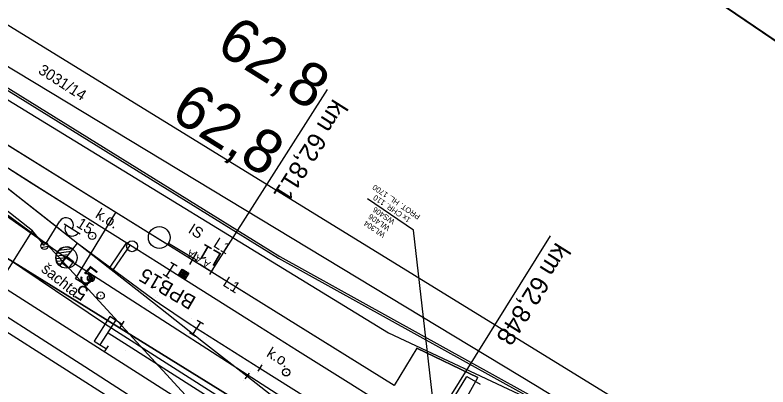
# Model space of a CAD drawing. Extents: x -621145 to -620110, y -1122807 to -1121971.
# Drawn here: x -620819.9 to -620716.5, y -1122376.5 to -1122325.4 of the extents above; entities that cross this region are included whole.
import ezdxf

# ---------------------------------------------------------------- set-up
doc = ezdxf.new("R2010")
doc.units = 0
for name, color, linetype in [('060601_EOV', 7, 'Continuous'), ('060604_ROZVODY_SEE', 7, 'Continuous'), ('CETIN', 7, 'Continuous'), ('POPIS KABELOVÉ TRASY', 7, 'Continuous'), ('PS 06-14-01_trasa_sdělovací_nové', 7, 'Continuous'), ('RÁMY', 7, 'Continuous'), ('SEE', 7, 'Continuous'), ('SSZT', 7, 'Continuous'), ('SSZT-DK', 7, 'Continuous'), ('UZEMNĚNÍ', 7, 'Continuous'), ('Vrstva 1', 7, 'Continuous'), ('Vrstva 15', 7, 'Continuous'), ('Vrstva 2', 7, 'Continuous'), ('Vrstva 25', 7, 'Continuous'), ('Vrstva 27', 7, 'Continuous'), ('Vrstva 3', 7, 'Continuous'), ('Vrstva 47', 7, 'Continuous'), ('Vrstva 53', 7, 'Continuous'), ('Vrstva 55', 7, 'Continuous'), ('Vrstva 56', 7, 'Continuous'), ('Vrstva 57', 7, 'Continuous'), ('Vrstva 6', 7, 'Continuous'), ('Vrstva 62', 7, 'Continuous'), ('Vrstva 7', 7, 'Continuous'), ('ČD-T', 7, 'Continuous')]:
    doc.layers.add(name, color=color, linetype=linetype)

msp = doc.modelspace()

# ---------------------------------------------------------------- linework, layer by layer
at = {"layer": '060601_EOV'}
msp.add_lwpolyline([(-620599.21, -1122483.22), (-620683.52, -1122429.44), (-620756.33, -1122383.52), (-620765.8, -1122398.39), (-620784.65, -1122386.39), (-620822.22, -1122362.42), (-620817.53, -1122355.08), (-620826.41, -1122348.08), (-620839.92, -1122337.94), (-620848.84, -1122332), (-620848.83, -1122331.99)], dxfattribs=at)
at = {"layer": '060604_ROZVODY_SEE'}
msp.add_line((-620815.89, -1122357.08), (-620817.53, -1122355.08), dxfattribs=at)
msp.add_lwpolyline([(-620742.35, -1122414.85), (-620741.73, -1122413.88), (-620750.53, -1122408.25), (-620763.56, -1122399.82), (-620784.65, -1122386.39), (-620822.22, -1122362.42), (-620817.53, -1122355.08), (-620826.41, -1122348.08), (-620839.92, -1122337.94), (-620854.57, -1122328.18), (-620868.06, -1122319.69), (-620885.37, -1122308.82), (-620912.87, -1122291.53), (-620913.33, -1122292.25)], dxfattribs=at)
at = {"layer": 'CETIN'}
msp.add_lwpolyline([(-620926.41, -1122268.7), (-620748.44, -1122376.27), (-620484.52, -1122538.15)], dxfattribs=at)
at = {"layer": 'POPIS KABELOVÉ TRASY'}
for points in [[(-620761.06, -1122390.96), (-620765.21, -1122354.95), (-620771.53, -1122350.65)], [(-620771.53, -1122350.65), (-620771.53, -1122350.65)]]:
    msp.add_lwpolyline(points, dxfattribs=at)
at = {"layer": 'PS 06-14-01_trasa_sdělovací_nové'}
msp.add_lwpolyline([(-620756.33, -1122383.52), (-620759.75, -1122381.36), (-620756.35, -1122375.21), (-620764.72, -1122371.2), (-620767.85, -1122376.3), (-620853.07, -1122323.34), (-620895.69, -1122296.63), (-620912.11, -1122286.23), (-620914.88, -1122290.62), (-620933.41, -1122279.02)], dxfattribs=at)
at = {"layer": 'RÁMY'}
for points in [[(-621061.56, -1122093.92), (-620192.94, -1122683.83), (-620276.37, -1122806.68), (-621144.99, -1122216.77)], [(-620717.54, -1122148.04), (-620630.68, -1122207.04), (-620714.11, -1122329.88), (-620800.97, -1122270.89)], [(-620887.83, -1122211.9), (-620192.94, -1122683.83), (-620276.37, -1122806.68), (-620971.26, -1122334.75)]]:
    msp.add_lwpolyline(points, close=True, dxfattribs=at)
at = {"layer": 'SEE'}
msp.add_lwpolyline([(-620611.37, -1122497.7), (-620665.57, -1122462.75), (-620686.03, -1122449.83), (-620727.54, -1122423.18), (-620794.51, -1122379.86), (-620815.52, -1122356.95), (-620832.17, -1122344.66), (-620847.81, -1122332.59), (-620908.26, -1122294.69)], dxfattribs=at)
at = {"layer": 'SSZT'}
for points in [[(-620879.24, -1122313.32), (-620842.99, -1122336.61), (-620835.05, -1122343.25), (-620812.66, -1122358.95), (-620764.9, -1122389.75), (-620688.59, -1122438.97), (-620596.98, -1122496.73), (-620576.74, -1122509.48), (-620506.75, -1122556.12), (-620447.29, -1122593.62), (-620363.27, -1122647.56), (-620313.97, -1122679.22), (-620306.51, -1122669.29), (-620273.14, -1122696.27), (-620258.42, -1122709.14), (-620248.07, -1122696.09)], [(-620763.25, -1122378.91), (-620761.03, -1122380.27), (-620757.87, -1122375.08), (-620756.04, -1122376.12)], [(-620763.25, -1122378.91), (-620761.03, -1122380.27), (-620757.87, -1122375.08), (-620756.04, -1122376.12)]]:
    msp.add_lwpolyline(points, dxfattribs=at)
at = {"layer": 'SSZT-DK'}
msp.add_lwpolyline([(-620927.29, -1122269.99), (-620900.27, -1122286.47), (-620889.15, -1122293.45), (-620783.74, -1122358.82), (-620712.75, -1122398.18), (-620653.12, -1122435.23), (-620617.36, -1122456.74), (-620574.42, -1122482.6), (-620528.16, -1122511.11), (-620496.31, -1122530.83), (-620515.02, -1122558.81), (-620500.38, -1122568.61), (-620465.39, -1122591.45), (-620452.16, -1122605.02), (-620438.23, -1122615.5), (-620392.31, -1122655.21), (-620359.04, -1122685.8), (-620308.77, -1122717.8), (-620291.41, -1122732.21), (-620277.2, -1122744.11), (-620257.61, -1122720.05), (-620250.25, -1122710.72), (-620233.29, -1122724.26), (-620225.35, -1122731.56)], dxfattribs=at)
at = {"layer": 'UZEMNĚNÍ'}
msp.add_line((-620815.89, -1122357.08), (-620817.53, -1122355.08), dxfattribs=at)
msp.add_lwpolyline([(-620742.35, -1122414.85), (-620741.73, -1122413.88), (-620750.53, -1122408.25), (-620763.56, -1122399.82), (-620784.65, -1122386.39), (-620822.22, -1122362.42), (-620817.53, -1122355.08), (-620826.41, -1122348.08), (-620838.67, -1122338.88), (-620840.23, -1122340.95)], dxfattribs=at)
at = {"layer": 'Vrstva 1'}
for p, q in [((-620806.11, -1122352.53), (-620848.09, -1122326.43)), ((-620811.62, -1122361.66), (-620806.11, -1122352.53)), ((-620764.72, -1122371.2), (-620756.35, -1122375.21))]:
    msp.add_line(p, q, dxfattribs=at)
for points in [[(-620931.81, -1122276.66), (-620929.02, -1122278.42), (-620921.28, -1122283.3), (-620914.45, -1122287.58), (-620907.38, -1122292.04), (-620900.38, -1122296.43), (-620893.37, -1122300.83), (-620887.01, -1122304.84), (-620881.07, -1122308.56), (-620874.8, -1122312.5), (-620868.33, -1122316.57), (-620865.13, -1122318.58), (-620858.38, -1122322.84), (-620854.48, -1122325.28), (-620853.21, -1122326.08), (-620851.73, -1122327.01), (-620850.55, -1122327.76), (-620840.58, -1122334.05), (-620833.63, -1122338.43), (-620832.14, -1122339.37), (-620823.78, -1122344.63), (-620817.74, -1122348.46), (-620811.37, -1122352.45)], [(-620851.64, -1122327.08), (-620840.38, -1122334.59), (-620831.19, -1122341.26), (-620824.9, -1122346.12), (-620811.35, -1122356.78), (-620800.85, -1122364.55), (-620800.09, -1122365.07), (-620796.17, -1122367.69), (-620795.02, -1122368.44), (-620786.31, -1122373.93), (-620764.42, -1122387.67), (-620747.63, -1122398.19), (-620733.73, -1122406.89), (-620718.35, -1122416.52), (-620703.01, -1122426.15), (-620686.98, -1122436.2), (-620670.85, -1122446.34), (-620652.24, -1122458.03), (-620632.99, -1122470.12), (-620616.99, -1122480.17)], [(-620850.55, -1122327.76), (-620838.47, -1122335.9), (-620831.26, -1122341.18), (-620824.88, -1122346.1), (-620819.56, -1122350.3), (-620813.61, -1122354.97)], [(-620823.79, -1122344.63), (-620816.97, -1122348.94), (-620810.35, -1122353.09), (-620803.86, -1122357.18), (-620803.36, -1122357.5), (-620800.13, -1122359.53), (-620798.65, -1122360.46), (-620794.42, -1122363.12), (-620788.1, -1122367.1), (-620781.12, -1122371.5), (-620774.17, -1122375.88), (-620767.51, -1122380.06), (-620763.22, -1122382.76), (-620756.39, -1122387.05), (-620748.87, -1122391.78), (-620741.59, -1122396.35), (-620734.61, -1122400.75), (-620727.79, -1122405.03), (-620720.71, -1122409.49), (-620715.67, -1122412.65)], [(-620823.79, -1122344.63), (-620816.97, -1122348.94), (-620810.35, -1122353.09), (-620803.86, -1122357.18), (-620803.36, -1122357.5), (-620800.13, -1122359.53), (-620798.65, -1122360.46), (-620794.42, -1122363.12), (-620788.1, -1122367.1), (-620781.12, -1122371.5), (-620774.17, -1122375.88), (-620767.51, -1122380.06), (-620763.22, -1122382.76), (-620756.39, -1122387.05), (-620748.87, -1122391.78), (-620741.59, -1122396.35), (-620734.61, -1122400.75), (-620727.79, -1122405.03), (-620720.71, -1122409.49), (-620715.67, -1122412.65)], [(-620795.27, -1122359.26), (-620795.68, -1122359.01), (-620806.11, -1122352.53)], [(-620811.35, -1122356.78), (-620801.08, -1122364.82), (-620794.03, -1122370.35), (-620788.09, -1122375), (-620768.88, -1122390.1), (-620768.43, -1122390.45), (-620761.75, -1122395.7), (-620755.25, -1122400.95), (-620748.86, -1122405.85), (-620748.16, -1122406.32), (-620737.32, -1122413.73), (-620723.13, -1122422.77)], [(-620795.42, -1122358.82), (-620795.12, -1122359.01), (-620795.27, -1122359.26)], [(-620764.72, -1122371.2), (-620767.85, -1122376.3), (-620794.6, -1122359.68), (-620795.27, -1122359.26)], [(-620809.51, -1122361.58), (-620810.11, -1122362.57), (-620811.62, -1122361.66)], [(-620807.15, -1122369.06), (-620804.38, -1122370.84), (-620783.31, -1122384.28), (-620762.21, -1122397.72), (-620749.18, -1122406.14), (-620748.33, -1122406.68), (-620737.32, -1122413.73)], [(-620756.33, -1122383.52), (-620759.75, -1122381.36), (-620756.35, -1122375.21)]]:
    msp.add_lwpolyline(points, dxfattribs=at)
at = {"layer": 'Vrstva 15'}
for p, q in [((-620808.23, -1122370.75), (-620806.08, -1122367.38)), ((-620805.5, -1122368.34), (-620804.96, -1122367.5)), ((-620807.66, -1122371.71), (-620807.12, -1122370.87))]:
    msp.add_line(p, q, dxfattribs=at)
msp.add_lwpolyline([(-620805.23, -1122367.92), (-620806.92, -1122366.84), (-620809.07, -1122370.21), (-620807.39, -1122371.29)], dxfattribs=at)
at = {"layer": 'Vrstva 2'}
for p, q in [((-620811.98, -1122357.59), (-620811.35, -1122356.78)), ((-620798.85, -1122356.75), (-620795.42, -1122358.82)), ((-620812.07, -1122357.53), (-620813.96, -1122357.75)), ((-620813.79, -1122359.89), (-620811.98, -1122357.59)), ((-620812.57, -1122358.34), (-620814.33, -1122358.56)), ((-620812.9, -1122358.76), (-620814.33, -1122358.93)), ((-620812.24, -1122357.92), (-620814.23, -1122358.17)), ((-620795.94, -1122359.68), (-620794.91, -1122357.96)), ((-620813.22, -1122359.18), (-620814.23, -1122359.3)), ((-620813.55, -1122359.59), (-620814.02, -1122359.65)), ((-620796.1, -1122360.91), (-620797.46, -1122361.25)), ((-620796.18, -1122360.8), (-620797.45, -1122361.11)), ((-620796.33, -1122360.7), (-620797.35, -1122360.95)), ((-620796.49, -1122360.6), (-620797.26, -1122360.79)), ((-620796.65, -1122360.51), (-620797.16, -1122360.63)), ((-620796.81, -1122360.41), (-620797.06, -1122360.48)), ((-620809.97, -1122361.38), (-620809.83, -1122361.96)), ((-620809.82, -1122361.18), (-620809.6, -1122362.07)), ((-620809.63, -1122361.09), (-620809.39, -1122362.06)), ((-620809.43, -1122361.09), (-620809.21, -1122361.97)), ((-620809.2, -1122361.19), (-620809.05, -1122361.77)), ((-620796.2, -1122361.07), (-620797.3, -1122361.34)), ((-620796.29, -1122361.23), (-620797.14, -1122361.44)), ((-620796.39, -1122361.39), (-620796.98, -1122361.54)), ((-620796.49, -1122361.55), (-620796.82, -1122361.63)), ((-620796.58, -1122361.71), (-620796.66, -1122361.73)), ((-620786.04, -1122373.5), (-620786.58, -1122374.35)), ((-620787.78, -1122374.61), (-620788.39, -1122375.4))]:
    msp.add_line(p, q, dxfattribs=at)
for points in [[(-620811.35, -1122356.78), (-620800.85, -1122364.55), (-620800.09, -1122365.07), (-620796.17, -1122367.69), (-620795.02, -1122368.44), (-620786.31, -1122373.93)], [(-620811.35, -1122356.78), (-620801.08, -1122364.82), (-620794.03, -1122370.35), (-620788.09, -1122375)]]:
    msp.add_lwpolyline(points, dxfattribs=at)
msp.add_lwpolyline([(-620796.61, -1122361.76), (-620797.51, -1122361.22), (-620796.97, -1122360.32), (-620796.07, -1122360.86)], close=True, dxfattribs=at)
msp.add_lwpolyline([(-620796.61, -1122361.76), (-620797.51, -1122361.22), (-620796.97, -1122360.32), (-620796.07, -1122360.86)], close=True, dxfattribs=at)
for centre, radius in [((-620800.13, -1122355.98), 1.5), ((-620812.88, -1122358.74), 1.46), ((-620809.51, -1122361.58), 0.5)]:
    msp.add_circle(centre, radius, dxfattribs=at)
msp.add_arc((-620812.88, -1122358.74), 1.46, 51.965, 231.9259, dxfattribs=at)
at = {"layer": 'Vrstva 25'}
for p, q in [((-620815.64, -1122356.7), (-620813.78, -1122353.73)), ((-620813.18, -1122354.1), (-620810.98, -1122355.48)), ((-620816.38, -1122356.99), (-620815.53, -1122356.79)), ((-620816.34, -1122357.36), (-620815.4, -1122357.15))]:
    msp.add_line(p, q, dxfattribs=at)
msp.add_circle((-620815.9, -1122357.12), 0.5, dxfattribs=at)
for centre, start, end in [((-620812.93, -1122354.26), 327.9262, 147.9262), ((-620812.09, -1122354.8), 147.2236, 328.6287)]:
    msp.add_arc(centre, 1, start, end, dxfattribs=at)
at = {"layer": 'Vrstva 27'}
for p, q in [((-620809.4, -1122355.73), (-620809.31, -1122355.78)), ((-620782.74, -1122374.48), (-620782.65, -1122374.54))]:
    msp.add_line(p, q, dxfattribs=at)
for centre in [(-620809.35, -1122355.76), (-620782.69, -1122374.51)]:
    msp.add_circle(centre, 0.5, dxfattribs=at)
at = {"layer": 'Vrstva 3'}
for p, q in [((-620798.12, -1122359.61), (-620799.18, -1122361.3)), ((-620798.12, -1122359.61), (-620799.18, -1122361.3)), ((-620798.54, -1122359.35), (-620797.69, -1122359.88)), ((-620798.54, -1122359.35), (-620797.69, -1122359.88)), ((-620799.61, -1122361.04), (-620798.76, -1122361.57)), ((-620799.61, -1122361.04), (-620798.76, -1122361.57)), ((-620794.48, -1122367.6), (-620795.55, -1122369.29)), ((-620794.91, -1122367.33), (-620794.06, -1122367.86)), ((-620795.97, -1122369.02), (-620795.13, -1122369.56))]:
    msp.add_line(p, q, dxfattribs=at)
at = {"layer": 'Vrstva 47'}
msp.add_lwpolyline([(-620813.54, -1122359.46), (-620812.85, -1122358.55), (-620811.9, -1122359.3), (-620812.62, -1122360.2), (-620813.54, -1122359.46)], dxfattribs=at)
at = {"layer": 'Vrstva 53'}
for p, q in [((-620838.83, -1122326.12), (-620768.63, -1122369.09)), ((-620741.46, -1122408.09), (-620821.12, -1122358.76)), ((-620768.63, -1122369.09), (-620748.53, -1122378.52))]:
    msp.add_line(p, q, dxfattribs=at)
at = {"layer": 'Vrstva 55'}
for p, q in [((-620866.03, -1122298.98), (-620688.16, -1122408.5)), ((-620838.83, -1122326.12), (-620768.63, -1122369.09)), ((-620821.12, -1122358.76), (-620741.46, -1122408.09)), ((-620807.67, -1122367.84), (-620821.12, -1122358.76)), ((-620684.91, -1122455.63), (-620825.92, -1122365.89)), ((-620645.72, -1122471.03), (-620807.67, -1122367.84)), ((-620768.63, -1122369.09), (-620748.53, -1122378.52))]:
    msp.add_line(p, q, dxfattribs=at)
at = {"layer": 'Vrstva 56'}
for p, q in [((-620824.91, -1122364.39), (-620810.36, -1122373.73)), ((-620810.36, -1122373.73), (-620648.08, -1122477.56))]:
    msp.add_line(p, q, dxfattribs=at)
at = {"layer": 'Vrstva 6'}
for p, q in [((-620792.93, -1122360.66), (-620777, -1122335.65)), ((-620764.44, -1122384.69), (-620746.39, -1122355.76)), ((-620794.6, -1122359.6), (-620792.93, -1122360.66)), ((-620794.6, -1122359.6), (-620792.93, -1122360.66)), ((-620793.19, -1122361.08), (-620792.66, -1122360.23)), ((-620793.19, -1122361.08), (-620792.66, -1122360.23))]:
    msp.add_line(p, q, dxfattribs=at)
at = {"layer": 'Vrstva 62'}
for p, q in [((-620810.91, -1122356.2), (-620810.91, -1122356.2)), ((-620811.79, -1122357.35), (-620811.79, -1122357.35)), ((-620800.41, -1122364), (-620800.41, -1122364)), ((-620800.64, -1122364.24), (-620800.64, -1122364.24)), ((-620799.68, -1122364.49), (-620799.68, -1122364.49)), ((-620801.51, -1122365.39), (-620801.51, -1122365.39)), ((-620801.29, -1122365.11), (-620801.29, -1122365.11)), ((-620800.51, -1122365.65), (-620800.51, -1122365.65)), ((-620795.72, -1122367.14), (-620795.72, -1122367.14)), ((-620794.61, -1122367.87), (-620794.61, -1122367.87)), ((-620806.77, -1122368.47), (-620806.77, -1122368.47)), ((-620796.62, -1122368.25), (-620796.62, -1122368.25)), ((-620795.43, -1122369.02), (-620795.43, -1122369.02)), ((-620807.54, -1122369.66), (-620807.54, -1122369.66)), ((-620804.01, -1122370.23), (-620804.01, -1122370.23)), ((-620793.61, -1122369.77), (-620793.61, -1122369.77)), ((-620794.44, -1122370.94), (-620794.44, -1122370.94)), ((-620804.76, -1122371.45), (-620804.76, -1122371.45)), ((-620785.94, -1122373.33), (-620785.94, -1122373.33)), ((-620787.65, -1122374.43), (-620787.65, -1122374.43)), ((-620786.69, -1122374.53), (-620786.69, -1122374.53)), ((-620788.52, -1122375.57), (-620788.52, -1122375.57))]:
    msp.add_line(p, q, dxfattribs=at)
at = {"layer": 'Vrstva 7'}
for p, q in [((-620804.65, -1122356.69), (-620806.94, -1122360.04)), ((-620804.14, -1122357.01), (-620806.46, -1122360.4)), ((-620805.59, -1122358.59), (-620805.59, -1122358.59)), ((-620808.23, -1122363.94), (-620808.14, -1122363.99)), ((-620808.23, -1122363.94), (-620808.14, -1122363.99))]:
    msp.add_line(p, q, dxfattribs=at)
for centre, radius in [((-620803.86, -1122357.18), 0.75), ((-620803.86, -1122357.18), 0.75), ((-620808.18, -1122363.97), 0.5), ((-620808.18, -1122363.97), 0.5)]:
    msp.add_circle(centre, radius, dxfattribs=at)
at = {"layer": 'ČD-T'}
msp.add_lwpolyline([(-620927.12, -1122269.75), (-620900.08, -1122286.23), (-620888.96, -1122293.22), (-620783.56, -1122358.58), (-620712.56, -1122397.94), (-620652.93, -1122435), (-620617.18, -1122456.5), (-620574.24, -1122482.37), (-620527.97, -1122510.87), (-620481.08, -1122540.08), (-620497, -1122565.38), (-620499.27, -1122568.98), (-620465.21, -1122591.22), (-620451.97, -1122604.79), (-620438.05, -1122615.26), (-620392.12, -1122654.98), (-620358.85, -1122685.56), (-620308.58, -1122717.56), (-620291.22, -1122731.97), (-620279.98, -1122741.46), (-620260.48, -1122717.47), (-620252.94, -1122708.19), (-620233.1, -1122724.03), (-620225.18, -1122731.31)], dxfattribs=at)

# ---------------------------------------------------------------- texts
at = {"layer": 'POPIS KABELOVÉ TRASY'}
for s, p in [('PROT. HL. 1700', (-620764.18, -1122352.95)), ('1x CHR. 110', (-620765.51, -1122353.4)), ('WS406', (-620767.68, -1122353.62)), ('WL406', (-620768.36, -1122354.52)), ('WL304', (-620768.99, -1122355.45))]:
    msp.add_text(s, height=0.75, rotation=145.8181, dxfattribs=at).set_placement(p)
at = {"layer": 'Vrstva 2'}
msp.add_text('5', height=2.5, rotation=321.9459, dxfattribs=at).set_placement((-620811.35, -1122361.66))
at = {"layer": 'Vrstva 25'}
msp.add_text('15', height=1.5, rotation=327.9262, dxfattribs=at).set_placement((-620811.64, -1122354.44))
at = {"layer": 'Vrstva 27'}
for p in [(-620809.02, -1122353.16), (-620785.5, -1122372.24)]:
    msp.add_text('k.o.', height=1.5, rotation=328.4879, dxfattribs=at).set_placement(p)
at = {"layer": 'Vrstva 3'}
for s, height, rotation, p in [('IS', 1.5, 327.7899, (-620796.27, -1122355.23)), ('L1', 2, 149.8236, (-620791.41, -1122358.28)), ('BPB15', 2, 149.8236, (-620794.92, -1122364.27)), ('5', 2, 148.8786, (-620809.69, -1122363.11))]:
    msp.add_text(s, height=height, rotation=rotation, dxfattribs=at).set_placement(p)
at = {"layer": 'Vrstva 47'}
msp.add_text('šachta', height=1.5, rotation=321.6217, dxfattribs=at).set_placement((-620816.47, -1122360.55))
at = {"layer": 'Vrstva 57'}
msp.add_text('3031/14', height=1.5, rotation=327.3665, dxfattribs=at).set_placement((-620816.87, -1122333.33))
at = {"layer": 'Vrstva 6'}
for s, height, rotation, p in [('km 62,811', 2.5, 237.7824, (-620776.22, -1122336.8)), ('L1', 1.5, 327.7824, (-620792.81, -1122357.16)), ('km 62,848', 2.5, 237.7824, (-620745.61, -1122356.52)), ('  A A A ', 1, 147.7824, (-620792.39, -1122359.81)), ('  A A ', 1, 147.7824, (-620792.39, -1122359.81)), ('L1', 1.5, 327.7824, (-620791.51, -1122362.53))]:
    msp.add_text(s, height=height, rotation=rotation, dxfattribs=at).set_placement(p)
at = {"layer": 'Vrstva 7'}
for rotation, p in [(327.8433, (-620792.54, -1122330.3)), (327.7881, (-620798.8, -1122339.47))]:
    msp.add_text('62,8', height=6, rotation=rotation, dxfattribs=at).set_placement(p)

doc.saveas('drawing.dxf')
